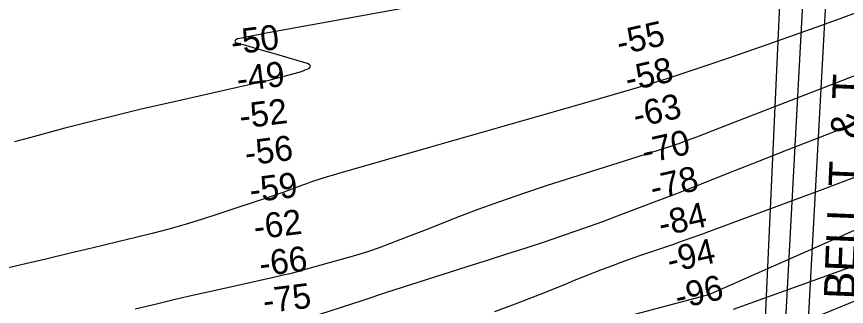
# Model space of a CAD drawing. Extents: x 3651524 to 3689615, y 505651 to 531377.
# Drawn here: x 3669026 to 3671256, y 514269 to 515048 of the extents above; entities that cross this region are included whole.
import ezdxf

# ---------------------------------------------------------------- set-up
doc = ezdxf.new("R2010")
doc.units = 0
for name, color, linetype in [('V-RIVR-RANG', 7, 'Continuous'), ('V-TOPO-MAJR', 7, 'Continuous'), ('V-TOPO-MINR', 7, 'Continuous'), ('V-UTIL-IDEN', 7, 'Continuous'), ('V-UTIL-LINE', 7, 'Continuous')]:
    doc.layers.add(name, color=color, linetype=linetype)

msp = doc.modelspace()

# ---------------------------------------------------------------- linework, layer by layer
at = {"layer": 'V-TOPO-MAJR'}
for points in [[(3670072.436, 515071.533), (3669692.336, 515002.042), (3669686.577, 515000.979), (3669680.821, 514999.903), (3669675.068, 514998.809), (3669669.317, 514997.701), (3669621.564, 514988.421), (3669619.112, 514987.7), (3669614.725, 514985.31), (3669612.79, 514983.64), (3669612.021, 514980.634), (3669612.816, 514979.45), (3669614.201, 514978.426), (3669647.558, 514968.934), (3669666.752, 514963.457), (3669685.941, 514957.961), (3669705.122, 514952.435), (3669724.297, 514946.89), (3669809.181, 514922.274), (3669812.994, 514918.888), (3669814.778, 514915.355), (3669813.518, 514911.604), (3669810.228, 514907.706), (3669800.543, 514903.616), (3669790.737, 514899.87), (3669780.749, 514896.642), (3669770.64, 514893.758), (3669710.272, 514878.232), (3669703.219, 514876.453), (3669696.155, 514874.716), (3669689.075, 514873.046), (3669681.984, 514871.418), (3669429.236, 514814.629), (3669360.637, 514798.805), (3669292.164, 514782.464), (3669223.882, 514765.346), (3669155.726, 514747.71), (3669074.133, 514726.101), (3669046.917, 514718.714), (3669019.765, 514711.104)], [(3671809.513, 514709.141), (3670888.988, 514301.929), (3670882.098, 514299.781), (3670875.186, 514297.706), (3670868.243, 514295.739), (3670861.279, 514293.844), (3670588.915, 514222.042)]]:
    msp.add_lwpolyline(points, dxfattribs=at)
at = {"layer": 'V-TOPO-MINR'}
for points in [[(3671706.701, 515213.451), (3671188.221, 515024.24), (3671114.885, 514997.816), (3671041.408, 514971.793), (3670967.721, 514946.371), (3670893.894, 514921.35), (3670770.411, 514880.061), (3670758.197, 514876.06), (3670745.951, 514872.16), (3670733.659, 514868.411), (3670721.336, 514864.763), (3670545.574, 514813.9), (3670445.33, 514784.948), (3670345.067, 514756.066), (3670244.774, 514727.289), (3670144.46, 514698.582), (3669887.842, 514625.29), (3669873.893, 514621.211), (3669859.98, 514617.017), (3669846.121, 514612.649), (3669832.297, 514608.166), (3669818.527, 514603.519), (3669804.793, 514598.771), (3669791.112, 514593.869), (3669777.468, 514588.865), (3669751.094, 514579.026), (3669742.15, 514575.743), (3669733.183, 514572.525), (3669724.182, 514569.402), (3669715.159, 514566.342), (3669566.19, 514516.718), (3669522.607, 514502.745), (3669478.831, 514489.433), (3669434.765, 514477.113), (3669390.506, 514465.455), (3669346.079, 514454.39), (3669301.622, 514443.452), (3669257.117, 514432.705), (3669212.581, 514422.085), (3669170.113, 514412.056), (3669104.31, 514396.558), (3669038.494, 514381.117), (3668972.659, 514365.758)], [(3671416.069, 514942.76), (3670935.058, 514756.026), (3670914.558, 514748.083), (3670894.051, 514740.159), (3670873.533, 514732.261), (3670853.009, 514724.381), (3670825.321, 514713.773), (3670818.621, 514711.252), (3670811.9, 514708.785), (3670805.151, 514706.399), (3670798.381, 514704.068), (3670787.118, 514700.265), (3670782.496, 514698.751), (3670449.176, 514592.832), (3670387.546, 514572.579), (3670326.2, 514551.524), (3670265.279, 514529.268), (3670204.642, 514506.211), (3670139.543, 514480.723), (3670111.66, 514469.83), (3670083.766, 514458.965), (3670055.856, 514448.142), (3670027.935, 514437.348), (3669999.869, 514426.987), (3669971.621, 514417.174), (3669943.101, 514408.184), (3669914.399, 514399.743), (3669794.725, 514366.424), (3669777.171, 514361.685), (3669759.571, 514357.131), (3669741.901, 514352.853), (3669724.185, 514348.76), (3669560.694, 514312.336), (3669506.471, 514300.081), (3669452.3, 514287.604), (3669398.206, 514274.794), (3669344.164, 514261.763)], [(3671389.051, 514802.361), (3671098.259, 514689.571), (3671050.535, 514670.992), (3671002.843, 514652.334), (3670955.197, 514633.558), (3670907.582, 514614.702), (3670838.522, 514587.256), (3670825.448, 514582.095), (3670812.358, 514576.976), (3670799.244, 514571.919), (3670786.113, 514566.902), (3670651.358, 514515.786), (3670600.287, 514496.807), (3670549.052, 514478.292), (3670497.572, 514460.47), (3670445.928, 514443.112), (3670394.134, 514426.184), (3670342.304, 514409.367), (3670290.421, 514392.716), (3670238.501, 514376.177), (3670213.431, 514368.235), (3670148.974, 514347.732), (3670084.55, 514327.126), (3670020.175, 514306.368), (3669955.833, 514285.507), (3669839.475, 514247.631)], [(3671295.796, 514622.714), (3671182.088, 514579.818), (3671068.226, 514537.327), (3670891.975, 514472.09), (3670866.088, 514462.621), (3670840.154, 514453.284), (3670814.149, 514444.147), (3670788.096, 514435.141), (3670699.963, 514405.055), (3670674.617, 514396.222), (3670649.349, 514387.175), (3670624.199, 514377.808), (3670599.126, 514368.226), (3670574.137, 514358.421), (3670549.183, 514348.531), (3670524.279, 514338.513), (3670499.409, 514328.41), (3670430.088, 514300.044), (3670370.208, 514276.798), (3670309.828, 514255.019)], [(3671394.997, 514420.608), (3670951.027, 514261.249)], [(3671290.654, 514288.944), (3671164.546, 514236.483)]]:
    msp.add_lwpolyline(points, dxfattribs=at)
at = {"layer": 'V-UTIL-LINE'}
for p, q in [((3671004.61, 513498.805), (3671112.337, 515861.622)), ((3671052.111, 513497.613), (3671181.383, 515860.43)), ((3671114.334, 513513.17), (3671243.607, 515875.984))]:
    msp.add_line(p, q, dxfattribs=at)

# ---------------------------------------------------------------- texts
at = {"layer": 'V-RIVR-RANG'}
for s, rotation, p in [('-55', 12.819611, (3670645.881, 514943.68)), ('-50', 7.131917, (3669605.784, 514944.979)), ('-49', 7.131917, (3669621.095, 514846.115)), ('-58', 12.819611, (3670668.857, 514846.352)), ('-63', 12.819611, (3670690.29, 514748.673)), ('-52', 7.131917, (3669628.291, 514746.236)), ('-56', 7.131917, (3669643.079, 514647.307)), ('-70', 12.819611, (3670714.037, 514651.521)), ('-78', 12.819611, (3670736.242, 514554.017)), ('-59', 7.131917, (3669655.511, 514548.083)), ('-84', 12.819611, (3670758.446, 514456.514)), ('-62', 7.131917, (3669666.895, 514448.728)), ('-94', 12.819611, (3670781.423, 514359.186)), ('-66', 7.131917, (3669681.683, 514349.799)), ('-96', 12.819611, (3670803.112, 514261.565)), ('-75', 7.131917, (3669691.759, 514250.281))]:
    msp.add_text(s, height=67, rotation=rotation, dxfattribs=at).set_placement(p)
at = {"layer": 'V-UTIL-IDEN'}
msp.add_text('S. BELL T. & T.', height=82.99983, rotation=87.616334, dxfattribs=at).set_placement((3671271.814, 514151.887))

doc.saveas('drawing.dxf')
